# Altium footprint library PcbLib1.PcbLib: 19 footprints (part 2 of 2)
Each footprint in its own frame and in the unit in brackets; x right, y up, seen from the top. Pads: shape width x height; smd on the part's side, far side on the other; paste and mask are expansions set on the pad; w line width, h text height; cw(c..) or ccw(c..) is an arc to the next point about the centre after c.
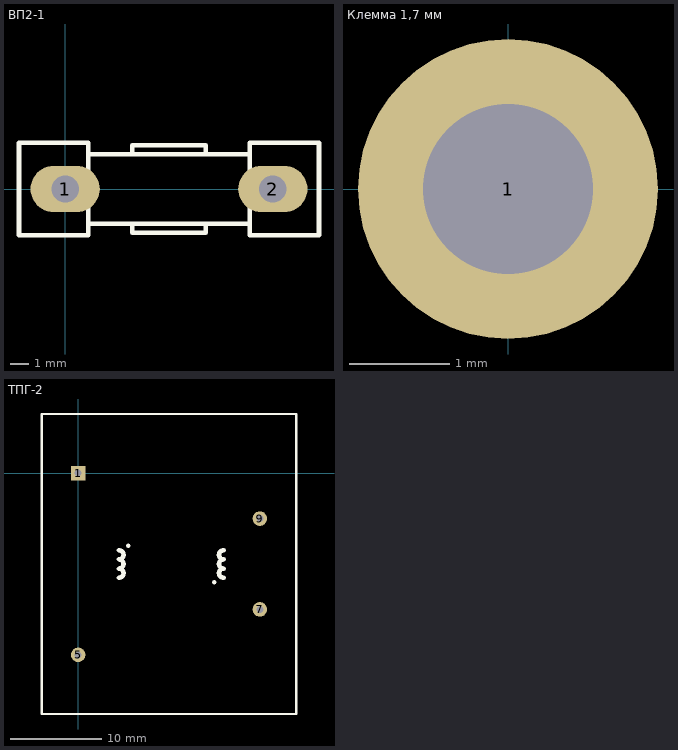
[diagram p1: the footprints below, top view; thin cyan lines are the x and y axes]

## ВП2-1 [mm]
height 10
pads (2):
  oval 3.81x2.54 hole 1.508: 1(0,0) 2(11.43,0)
Top Overlay:
  lines w0.254: 1.27,-1.905 10.16,-1.905 ; 1.27,1.905 10.16,1.905 ; 3.683,-1.905 3.683,-2.413 7.747,-2.413 7.747,-1.905 ; 3.683,1.905 3.683,2.413 7.747,2.413 7.747,1.905 ; -2.54,-2.54 -2.54,2.54 1.27,2.54 1.27,-2.54 -2.54,-2.54 ; 10.16,-2.54 10.16,2.54 13.97,2.54 13.97,-2.54 10.16,-2.54
3D body: height 0.9, standoff -7.1, extent -2.419,-2.1 13.881,2.1

## Клемма 1,7 мм [mm]
pads (1):
  round 3 hole 1.7: 1(0,0)

## ТПГ-2 [mm]
height 29.5
pads (4):
  rect 1.6x1.6 hole 0.8: 1(0,0)
  round 1.6 hole 0.8: 5(0,-20) 7(20,-15) 9(20,-5)
Top Overlay:
  lines w0.25: -4,-26.5 -4,6.5 24,6.5 24,-26.5 -4,-26.5
  lines w0.5: 4.5,-11.5 ccw(c4.5,-11) 4.5,-10.5 ccw(c4.5,-10) 4.5,-9.5 ccw(c4.5,-9) 4.5,-8.5 ; 16,-11.5 cw(c16,-11) 16,-10.5 cw(c16,-10) 16,-9.5 cw(c16,-9) 16,-8.5 ; 5.5,-8 5.5,-8 ; 15,-12 15,-12
3D body: height 29.5, standoff -5, extent -4,-26.5 24,6.5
